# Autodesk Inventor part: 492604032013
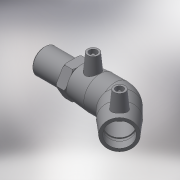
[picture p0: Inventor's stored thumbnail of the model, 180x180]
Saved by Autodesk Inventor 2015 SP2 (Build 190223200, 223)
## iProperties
Created: 2017-06
Part Number: 492604032013
Material: Generic
Description: PLASSON 45° ELBOW TRANSITION MALE 32-1.1/4"
Document SubType Name: Modeling
Designer: KIM
Mass: 123.605 g
Surface Area: 366.818 cm^2
Volume: 123.605 cm^3
Density: 1 g/cm^3
Appearance: Default
Author: KIM
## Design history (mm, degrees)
derived "492604.ipt"
feature "Solid1::492604.ipt"
tag "TaggingFeature1"
body "Solid1"
other parameters: "d2" = 44, "d4" = 23.5, "d5" = 39.6, "d8" = 168 deg, "d10" = 15.6, "d11" = 5.2, "d29" = 43, "d30" = 15, "d31" = 32.9, "d34" = 5 deg, "d41" = 4, "d42" = 14, "d43" = 0, "d49" = 32, "d50" = 20.8, "d51" = 15.6, "d52" = 40.17, "d54" = 135 deg, "d86" = 19.8, "d87" = 135 deg, "d88" = 94, "d90" = 39, "d91" = 0, "d92" = 39, "d93" = 0, "d101" = 3, "d102" = 0, "d107" = 0.1, "d108" = 23, "d109" = 41.91, "d110" = 36, "d111" = 9, "d112" = 52.8, "d113" = 29.337, "d114" = 32.4, "d116" = 1.32, "d122" = 0, "d123" = 2.0955, "d_" = 32, "L_1" = 39, "D_" = 23, "A_" = 43, "d_2" = 12, "L_2" = 36, "R_" = 41.91, "D_1" = 44
